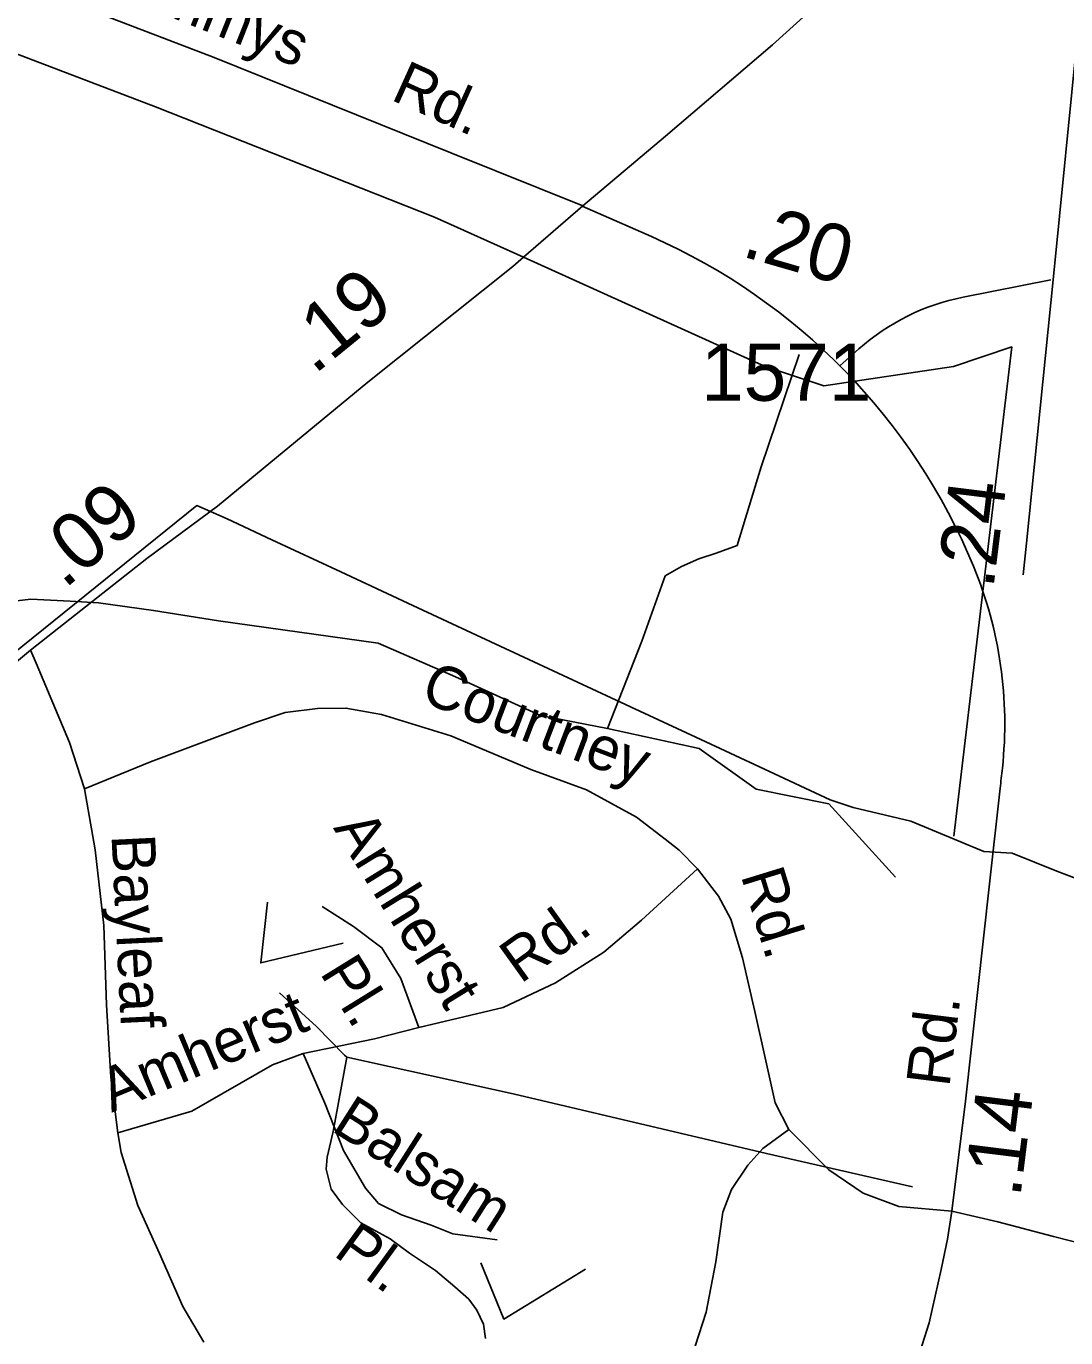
# Model space of a CAD drawing. Extents: x 2315291 to 2336543, y 597177 to 615230.
# Drawn here: x 2325292 to 2327561, y 599483 to 602347 of the extents above; entities that cross this region are included whole.
import ezdxf

# ---------------------------------------------------------------- set-up
doc = ezdxf.new("R2010")
doc.units = 0
for name, color, linetype in [('Exist Boundary Political City Limit New', 7, 'Continuous'), ('Exist Boundary Political Urban Extension UEB', 7, 'Continuous'), ('Exist Hydrographic Misc Water Feature', 7, 'Continuous'), ('Exist Road Non-System Type 51', 7, 'Continuous'), ('Exist Road Non-System Type 51 Label', 7, 'Continuous'), ('Exist Road Primary US Attributed', 7, 'Continuous'), ('Exist Road Primary US Mileage Tenths English Label', 7, 'Continuous'), ('Exist Road Secondary Mileage Hundredths English Label', 7, 'Continuous'), ('Exist Road Secondary Type 51 Attributed', 7, 'Continuous'), ('Exist Road Secondary Type 51 Label', 7, 'Continuous'), ('Exist Road Secondary Type 51 Number Label', 7, 'Continuous'), ('Map Preparation Boundary City Limit Buffer Line', 7, 'Continuous')]:
    doc.layers.add(name, color=color, linetype=linetype)

msp = doc.modelspace()

# ---------------------------------------------------------------- linework, layer by layer
at = {"layer": 'Exist Boundary Political City Limit New'}
msp.add_lwpolyline([(2327632, 600467.4), (2327541.5, 600502.1), (2327443.8, 600541), (2327381.8, 600544.7), (2327223, 600610.9), (2327096.8, 600640.9), (2327046.8, 600657.7), (2326903, 600724.6), (2326753.2, 600794.3), (2326611.2, 600860.6), (2326494.8, 600914.8), (2326389, 600964.1), (2326275, 601017.1), (2326135.5, 601082.1), (2325978.2, 601155.4), (2325828.2, 601225.3), (2325730.2, 601270.9), (2325664.2, 601300), (2324858.5, 600651.2)], dxfattribs=at)
at = {"layer": 'Exist Boundary Political Urban Extension UEB'}
for points in [[(2323172.1, 603492.9), (2323308.6, 603366.5), (2323549.3, 603154.1), (2323860.8, 602970.1), (2324158.2, 602771.8), (2324852, 602446.2), (2325574.1, 602170.2), (2326183, 601929.5), (2326377, 601842)], [(2326377, 601842), (2326905.1, 601603.9), (2327032.6, 601561.4), (2327315.8, 601603.9), (2327443.2, 601646.3), (2327316.7, 600578.5)]]:
    msp.add_lwpolyline(points, dxfattribs=at)
at = {"layer": 'Exist Hydrographic Misc Water Feature'}
for points in [[(2326979, 601629.7), (2326895.8, 601384.7), (2326843.9, 601212.5), (2326798.2, 601195.9), (2326759.8, 601183.4), (2326721.9, 601167.2), (2326686.2, 601146.6), (2326635.8, 601004.2), (2326560.3, 600813.6)], [(2326560.3, 600813.6), (2326414.1, 600842), (2326229.1, 600925.8), (2326060.4, 600999.9), (2325711.8, 601048.3), (2325569.9, 601070.9), (2325449.3, 601087.4), (2325387.4, 601091), (2325301.7, 601095.8), (2325227.9, 601087.1), (2325171.9, 601084.6), (2325115.9, 601075.9), (2325050.1, 601053.4), (2325000.3, 601042.6), (2324944.7, 601012.1), (2324889.1, 600989.6), (2324857.1, 600969.3), (2324837.5, 600954.8), (2324819.4, 600938.9)], [(2327189.2, 600488.6), (2327043.6, 600648.8), (2326885.5, 600681.1), (2326760.4, 600769.6), (2326560.3, 600813.6)], [(2325844.5, 600236.3), (2325925.5, 600162.9), (2325986.4, 600099.8), (2325991.9, 600095.7)], [(2325991.9, 600095.7), (2325962, 599933.5), (2325948.4, 599877.6), (2325946.8, 599851.5), (2325957.2, 599807.7), (2325981.9, 599774), (2326022, 599734.3), (2326086.2, 599699.1), (2326128.7, 599667.6), (2326184.9, 599629.9), (2326227.3, 599594.7), (2326257.7, 599567.1), (2326275.7, 599543.2), (2326289.8, 599513.1), (2326294.4, 599481.2)], [(2327226.3, 599813), (2326907.9, 599885.7), (2326354.8, 600015.6), (2325991.9, 600095.7)]]:
    msp.add_lwpolyline(points, dxfattribs=at)
at = {"layer": 'Exist Road Non-System Type 51'}
for p, q in [((2325301.4, 600984), (2325308.9, 600966.4)), ((2325308.9, 600966.4), (2325313.2, 600956.2))]:
    msp.add_line(p, q, dxfattribs=at)
for points in [[(2325313.2, 600956.2), (2325386.6, 600783.1), (2325419, 600681.7)], [(2326757.1, 600506.8), (2326717.2, 600547.7), (2326686.3, 600571.6), (2326623.7, 600619.8), (2326514.5, 600679.4), (2326393.3, 600723.5), (2326219, 600797.4), (2326067, 600843.9), (2325989.6, 600857.9), (2325927.9, 600856.7), (2325857, 600848), (2325790.1, 600825.7), (2325563, 600740.5), (2325419, 600681.7)], [(2325419, 600681.7), (2325442.1, 600548.6), (2325461.1, 600383.2), (2325466.8, 600210.1), (2325476.3, 600052.3), (2325491.5, 599930.6)], [(2326149, 600160.7), (2326333, 600203.9), (2326447.4, 600257.7), (2326552.6, 600325.3), (2326634.5, 600394.7), (2326757.1, 600506.8)], [(2326757.1, 600506.8), (2326802.7, 600446.9), (2326829.9, 600396.7), (2326855.1, 600312.4), (2326882.2, 600195.7), (2326906, 600088.1), (2326926.4, 599996), (2326956.6, 599938.2)], [(2326149, 600160.7), (2326109.6, 600267.7), (2326068.2, 600334.8), (2326006.5, 600381.3), (2325938.1, 600425)], [(2325896.3, 600103.6), (2326052.1, 600136), (2326149, 600160.7)], [(2325491.5, 599930.6), (2325653, 599978.1), (2325829.7, 600078.9), (2325896.3, 600103.6)], [(2325896.3, 600103.6), (2325943.8, 599995.3), (2325984.7, 599892), (2326032.7, 599809.5), (2326061.1, 599776.1), (2326111, 599751.9), (2326175.6, 599729), (2326223.1, 599710), (2326320, 599696.7)], [(2326743.8, 599440), (2326776.1, 599538.9), (2326797, 599649.2), (2326812.2, 599757.6), (2326831.2, 599807), (2326867.3, 599860.2), (2326899.6, 599896.4), (2326956.6, 599938.2)], [(2326956.6, 599938.2), (2327043.5, 599850), (2327118.6, 599799), (2327196.3, 599769.6), (2327312, 599759.5)], [(2325491.5, 599930.6), (2325499.1, 599887.8), (2325535.2, 599771.8), (2325582.7, 599667.2), (2325634, 599551.2), (2325679.6, 599473.3)], [(2327312, 599759.5), (2327412.7, 599736.6), (2327534.4, 599704.3), (2327637, 599677.7), (2327718.7, 599643.5)]]:
    msp.add_lwpolyline(points, dxfattribs=at)
at = {"layer": 'Exist Road Non-System Type 51 Label'}
for points in [[(2325818.8, 600433.8), (2325803.6, 600301.6), (2325983.5, 600344.9)], [(2326512.6, 599632.8), (2326334.4, 599523.8), (2326284.2, 599646.7)]]:
    msp.add_lwpolyline(points, dxfattribs=at)
at = {"layer": 'Exist Road Primary US Attributed'}
for p, q in [((2326505.7, 601953.6), (2326656.4, 601887.2)), ((2327337.1, 601755.1), (2327528.3, 601792.9)), ((2327067.8, 601605.2), (2327109.4, 601642.1)), ((2327417.8, 600682.7), (2327394.7, 600474))]:
    msp.add_line(p, q, dxfattribs=at)
for points in [[(2326507.1, 601954.4), (2326687.2, 602106.2), (2326920.6, 602305.6), (2327025.6, 602400.6), (2327204, 602575.8), (2327489.1, 602864.4), (2327740.8, 603109.6)], [(2326218.6, 602070.4), (2326507.1, 601954.4)], [(2321872.6, 598168.2), (2322100.6, 598357.7), (2322368.8, 598574.3), (2322589.4, 598759.9), (2322822.5, 598950.5), (2322989.6, 599086.8), (2323103.2, 599177.4), (2323552, 599546.7), (2323723.6, 599695.4), (2324757.7, 600529.3), (2324925.6, 600670.6), (2324932.1, 600676), (2324968.9, 600707), (2325301.4, 600984), (2325554.9, 601184.8), (2325709, 601298.4), (2326037.4, 601569.3), (2326353.8, 601821.9), (2326377, 601842), (2326507.1, 601954.4)], [(2327468.2, 601148.6), (2327475.3, 601218.2)]]:
    msp.add_lwpolyline(points, dxfattribs=at)
for centre, radius, start, end in [((2326112, 600651.8), 1350, 22.4692, 66.2198), ((2327431.3, 601279.3), 485, 101.1907, 131.579), ((2326527.8, 600823.8), 900, 353.8058, 22.4692), ((2306757.9, 602969.5), 20786, 353.68387, 353.80575)]:
    msp.add_arc(centre, radius, start, end, dxfattribs=at)
at = {"layer": 'Exist Road Secondary Type 51 Attributed'}
for points in [[(2327534.4, 601799.8), (2327587.6, 602334.2), (2327633.2, 602657.4), (2327646.6, 602722.5)], [(2325206.8, 602468.2), (2325701.9, 602278), (2326218.6, 602070.4)], [(2327475.3, 601218.2), (2327534.4, 601799.8)], [(2325948.1, 597529.5), (2326033.1, 597602.2), (2326171.8, 597727.7), (2326238.3, 597789.5), (2326282, 597838.9), (2326346.6, 597934), (2326570.9, 598270.6), (2326778, 598599.5), (2327008, 598966.5), (2327169.5, 599253.7), (2327217, 599371.6), (2327262.6, 599516.1), (2327289.2, 599632.1), (2327302.5, 599698.6), (2327312, 599759.5), (2327342.4, 600000), (2327394.7, 600474)]]:
    msp.add_lwpolyline(points, dxfattribs=at)
at = {"layer": 'Map Preparation Boundary City Limit Buffer Line'}
msp.add_lwpolyline([(2327632, 600467.4), (2327541.5, 600502.1), (2327443.8, 600541), (2327381.8, 600544.7), (2327223, 600610.9), (2327096.8, 600640.9), (2327046.8, 600657.7), (2326903, 600724.6), (2326753.2, 600794.3), (2326611.2, 600860.6), (2326494.8, 600914.8), (2326389, 600964.1), (2326275, 601017.1), (2326135.5, 601082.1), (2325978.2, 601155.4), (2325828.2, 601225.3), (2325730.2, 601270.9), (2325664.2, 601300), (2324858.5, 600651.2)], dxfattribs=at)

# ---------------------------------------------------------------- texts
at = {"layer": 'Exist Road Non-System Type 51 Label'}
for s, rotation, p in [('Courtney', 339.1158, (2326149.1, 600873.6)), ('Amherst', 301.7174, (2325961, 600596.1)), ('Bayleaf', 272.837, (2325477.8, 600580.6)), ('Rd.', 287.108, (2326851.1, 600492.8)), ('Rd.', 35.5562, (2326370.7, 600254.6)), ('Pl.', 301.7174, (2325931.3, 600280)), ('Amherst', 22.665, (2325478, 599974.3)), ('Balsam', 327.4909, (2325955.5, 599936.3)), ('Pl.', 323.9293, (2325960, 599664.1))]:
    msp.add_text(s, height=95, rotation=rotation, dxfattribs=at).set_placement(p)
at = {"layer": 'Exist Road Primary US Mileage Tenths English Label'}
for s, rotation, p in [('.19', 39.2109, (2325920.4, 601584.4)), ('.09', 40.2482, (2325375.2, 601116.3))]:
    msp.add_text(s, height=125, rotation=rotation, dxfattribs=at).set_placement(p)
at = {"layer": 'Exist Road Secondary Mileage Hundredths English Label'}
for s, rotation, p in [('.20', 343.8993, (2326850.4, 601845.1)), ('.24', 82.8984, (2327402.7, 601116.3)), ('.14', 82.8984, (2327461.5, 599787.2))]:
    msp.add_text(s, height=125, rotation=rotation, dxfattribs=at).set_placement(p)
at = {"layer": 'Exist Road Secondary Type 51 Label'}
for s, rotation, p in [('Tommys', 338.3192, (2325432.8, 602435.4)), ('Rd.', 335.6739, (2326085, 602187)), ('Rd.', 82.8983, (2327306.7, 600028.7))]:
    msp.add_text(s, height=95, rotation=rotation, dxfattribs=at).set_placement(p)
at = {"layer": 'Exist Road Secondary Type 51 Number Label'}
msp.add_text('1571', height=125, dxfattribs=at).set_placement((2326764.8, 601528.8))

doc.saveas('drawing.dxf')
